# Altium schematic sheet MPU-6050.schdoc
size 217 x 72 mm
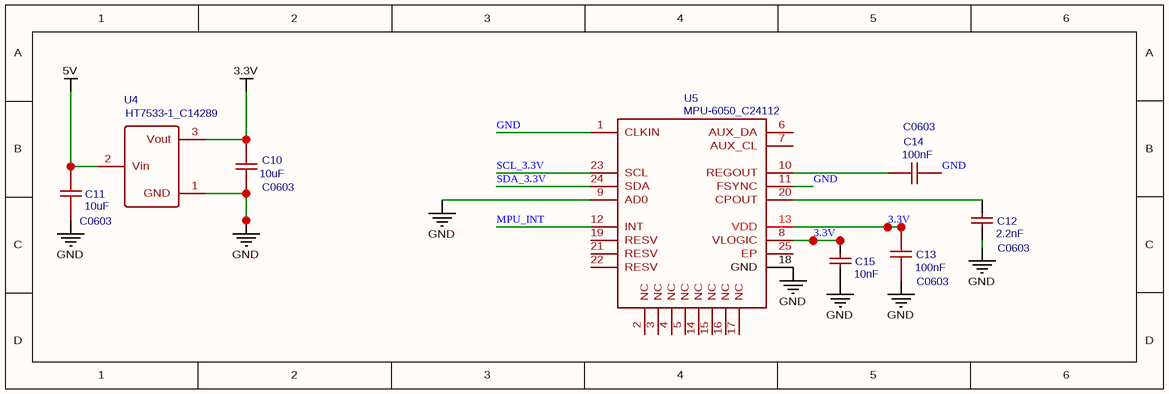
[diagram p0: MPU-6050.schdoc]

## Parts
C10  10uF  [C0603]
C11  10uF  [C0603]
C12  2.2nF  [C0603]
C13  100nF  [C0603]
C14  100nF  [C0603]
C15  10nF  [C0603]
U4  HT7533-1_C14289  [SOT-89-3_L4.5-W2.5-P1.50-LS4.2-BR]
U5  MPU-6050_C24112  [QFN-24_4X4X05P]

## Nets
3.3V: C10.2 C13.2 C15.2 U4.3(Vout) U5.8(VLOGIC) U5.13(VDD)
5V: C11.2 U4.2(Vin)
GND: C10.1 C11.1 C12.1 C13.1 C14.1 C15.1 U4.1(GND) U5.1(CLKIN) U5.9(AD0) U5.11(FSYNC) U5.18(GND)
MPU_INT: U5.12(INT)
SCL_3.3V: U5.23(SCL)
SDA_3.3V: U5.24(SDA)
NetC12_2: C12.2 U5.20(CPOUT)
NetC14_2: C14.2 U5.10(REGOUT)

Not connected (* = marked no-connect by the designer): U5 2(NC) 3(NC) 4(NC) 5(NC) 6(AUX_DA) 7(AUX_CL) 14(NC) 15(NC) 16(NC) 17(NC) 19(RESV) 21(RESV) 22(RESV) 25(EP)

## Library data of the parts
C10 C11 = 10uF: BOM_Manufacturer: SAMSUNG; BOM_Manufacturer Part: CL10A106KP8NNNC; nameAlias: Capacitance; SMT Type: Basic; Package Display: Yes
C12 = 2.2nF: BOM_Manufacturer: FH; BOM_Manufacturer Part: 0603B222K500NT; nameAlias: Capacitance; SMT Type: Basic; Package Display: Yes
C13 C14 = 100nF: BOM_Manufacturer: YAGEO; BOM_Manufacturer Part: CC0603KRX7R9BB104; nameAlias: Capacitance; SMT Type: Basic; Package Display: Yes
C15 = 10nF: BOM_Manufacturer: FH; BOM_Manufacturer Part: 0603B103K500NT; nameAlias: Capacitance; SMT Type: Basic
U4 = HT7533-1_C14289: BOM_Manufacturer: HOLTEK; SMT Type: Basic
U5 = MPU-6050_C24112: BOM_Manufacturer: InvenSense; sourceId: 1T5FDZYC8; SMT Type: Basic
